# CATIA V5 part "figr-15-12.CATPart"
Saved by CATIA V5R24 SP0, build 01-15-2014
Part number: Part1
Bounding box of the stored display mesh (mm): x -50 to 50, y -32.5 to 33.5, z -52 to 1
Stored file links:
  D:\KAVITA\CATIA V5-6R2014 Project_ Kavita\CATIA V5-6R2014_partfiles\Partfiles\c15_catia_v5-6r2014_prt\figr-15-12.CATPart
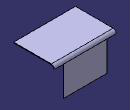
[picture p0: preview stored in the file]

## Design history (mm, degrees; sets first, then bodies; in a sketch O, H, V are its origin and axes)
SheetMetalParameters1: Thickness 1, BendRadius 4, KFactor 0.475772 {= log(min(100,max(20*SheetMetalParameters1.BendRadius,SheetMetalParameters1.Thickness)/SheetMetalParameters1.Thickness))/log(100)/2}, ReliefRadialLength 4, ReliefAxialLength 4, MinimumBendRadius 0
Body1 (main body)
  Sketch1 on xy-plane, origin (0, 0, 0), H (1, 0, 0), V (0, 1, 0)
    line L1 (-50, 32.5) -> (50, 32.5)
    line L2 (50, 32.5) -> (50, -32.5)
    line L3 (50, -32.5) -> (-50, -32.5)
    line L4 (-50, -32.5) -> (-50, 32.5)
    length L1 = 100
    length L2 = 65
    horizontal: L1 H, L3 H
    vertical: L2 V, L4 V
    symmetry: L4 L2 V, L1 L3 H
  Wall1: Thickness 1, Profile Sketch1
  d_NewWallOnEdge1: NewWallOnEdge_Edge edge [face of Wall1 | face of Wall1], NewWallOnEdge_Length 53, NewWallOnEdge_HeightLimitOffset 0, NewWallOnEdge_WidthOffset1 -15, NewWallOnEdge_WidthOffset2 -15, NewWallOnEdge_Angle 90, NewWallOnEdge_BendRadiusValue 4 {= SheetMetalParameters1.BendRadius}, NewWallOnEdge_BendTable SheetMetalParameters1, KFacteur 0.475772 {= log(min(100,max(20*d_NewWallOnEdge1.Radius,SheetMetalParameters1.Thickness)/SheetMetalParameters1.Thickness))/log(100)/2}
